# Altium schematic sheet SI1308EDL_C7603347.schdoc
size 127 x 101 mm
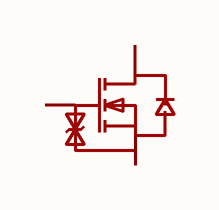
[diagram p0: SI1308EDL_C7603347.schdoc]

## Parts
Q?  si1308edl  [SOT-323-3_L2.0-W1.3-P1.30-LS2.1-BR]  (value not drawn)

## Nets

Not connected (* = marked no-connect by the designer): Q? 1(G) 2(S) 3(D)

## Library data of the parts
Q? = si1308edl: 漏源电压(Vdss):30V;连续漏极电流(Id):1.4A;导通电阻(RDS(on)):150mΩ@4.5V,0.5A;耗散功率(Pd):360mW;阈值电压(Vgs(th)):1.5V;; Manufacturer: TECH PUBLIC(台舟); Symbol: SI1308EDL_C7603347; AddInBom: yes; ModelId: 59529c0d6fc749f28f2d0659e12986b4; ModelName: SOT-323-3_L2.0-W1.3-H1.0-LS2.1-P1.30; ModelTransform: 78.74,82.677,0,90,0,0,0.0005,0,0; Drain to Source Voltage: 30V; Current - Continuous Drain(Id): 1.4A; Pd - Power Dissipation: 360mW; Gate Threshold Voltage (Vgs(th)): 1.5V; Gate Charge(Qg): 2.6nC@4.5V; Input Capacitance(Ciss): 146pF@15V; Reverse Transfer Capacitance (Crss@Vds): 14.8pF@15V; Output Capacitance(Coss): 18.3pF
